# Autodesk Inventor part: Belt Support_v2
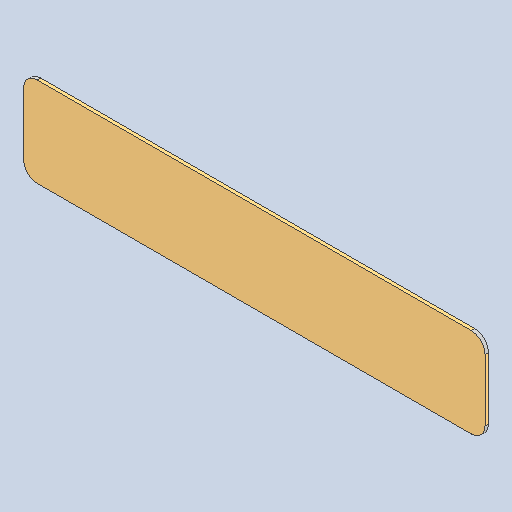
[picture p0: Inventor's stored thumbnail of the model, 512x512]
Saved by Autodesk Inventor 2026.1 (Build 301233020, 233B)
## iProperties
Created: 2026-10
Part Number: Belt Support_v2
Material: Generic
Document SubType Name: Modeling
Designer: hp
Density: 1 g/cm^3
Appearance: Default
Author: hp
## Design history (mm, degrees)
sketch "Sketch1"
  geometry: L1 (0, 0)-(670, 0); L2 (670, 0)-(670, 130); L3 (670, 130)-(0, 130); L4 (0, 130)-(0, 0)
  constraints: 8 end point, 2 parallel, 1 horizontal, 1 perpendicular
  dimensions: "d0" = 670 distance of L3.end L2.end; "d1" = 130 distance of L2.end L1.end
extrude "Extrusion1" new body sketch "Sketch1" distance "d2" = 5; taper "d3" = 0 deg
fillet "Fillet1" dims "d4" = 20
body "Solid1"
